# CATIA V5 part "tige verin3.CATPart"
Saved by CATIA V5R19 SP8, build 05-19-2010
Part number: tige verin3
Bounding box of the stored display mesh (mm): x 46.439 to 93.5, y -56.5 to -46.5, z 3.5 to 79.456
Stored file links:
  G:\EU_thinkMotion\CFAO_2010\MMS_groupe1\MMS_groupe1\A reprendre\OK\glenerrant\glenerrant\glenerrant\tige verin3.CATPart
  C:\Users\Gauthier\Documents\IFMA\Projet CFAO\glenerrant\Systeme.CATProduct
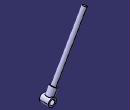
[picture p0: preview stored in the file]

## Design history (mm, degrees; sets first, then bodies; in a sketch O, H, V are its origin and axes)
Parameters
  `Longueur tige verin 3` = 69 mm {= `External.Longueur tige verin t`}
External parameters (linked from other documents)
  `External.Longueur tige verin t` = 69 mm
Set1
  Point1: (89, -51, 8)
  Point2: (5, -51, 154)
  Line1: type PtPt, FirstPoint Point2, SecondPoint Point1
  Plane1: type Normal, Curve Line1, RefPoint Point1
  Plane2: type Offset, RefPlane zx-plane, Offset -46.5
Body1 (main body)
  Sketch1 on Plane2, origin (0, -46.5, 0), H (-1, 0, 0), V (0, 0, 1)
    circle A1 centre (-89, 8) radius 3
    point P1 (-89, 8)
    reference projected point E1 (-89, 8) from Point1
    circle A2 centre (-89, 8) radius 4.5
    point P2 (-89, 8)
    reference projected point E2 (-89, 8) from Point1
    radius A1 = 3
    radius A2 = 4.5
    coincidence: P1 E1, E2 P2
  Pad1: profile Sketch1, direction (0, -1, 0), length 10
  Sketch2 on Plane1, origin (18.6759, 0, -32.4605), H (0, 1, 0), V (0.8668, 0, 0.4987)
    circle A1 centre (-51, 81.1328) radius 4
    point P1 (-51, 81.1328)
    reference projected point E1 (-51, 81.1328) from Point1
    radius A1 = 4
    coincidence: P1 E1
  Pad2: profile Sketch2, direction (-0.4987, 0, 0.8668), length 12, opposite side length -3
  Sketch3 on end face of Pad2, origin (12.6915, 0, -22.0591), H (0, -1, 0), V (0.8668, 0, 0.4987)
    circle A1 centre (51, 81.1328) radius 2.5
    point P1 (51, 81.1328)
    reference projected point E1 (51, 81.1328) from Point1
    radius A1 = 2.5
    coincidence: P1 E1
  Pad3: profile Sketch3, direction (-0.4987, 0, 0.8668), length 69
